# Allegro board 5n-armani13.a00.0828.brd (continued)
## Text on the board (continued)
IN2: list("[Spacing] IN2" "151.Shape to Route Keepin" "0 MIL [DEFAULT]" "0 MIL" "0.00 MIL" "DRC ERROR CLASS/IN2" "[Shape] Route Keepin/All ((-191.01 273.9) (8699.38 4792.96))" "[In2 Shape] GND ((-178.93 2335.01) (372.0 2675.16))" list(-117.680000 2460.370000) nil)@@@list("iris_chen" "2017/08/22 17:18:25" nil "P16C000357-PC" "5n-armani13.a00")@@@list("anson_lee" "2017/08/24 14:22:40" nil "P172000029-PC" "5n-armani13.a00.0824") | list("[Spacing] IN2" "17.Shape to Route Keepin" "0 MIL [DEFAULT]" "0 MIL" "0.00 MIL" "DRC ERROR CLASS/IN2" "[Shape] Route Keepin/All ((-191.01 273.9) (8699.38 4792.96))" "[In2 Shape] GND ((-190.82 3060.98) (345.0 3567.95))" list(-104.250000 3275.020000) nil)@@@list("iris_chen" "2017/08/24 17:07:00" nil "P16C000357-PC" "5n-armani13.a00")@@@list("anson_lee" "2017/08/24 14:34:00" nil "P172000029-PC" "5n-armani13.a00.0824") | list("[Spacing] IN2" "156.Shape to Route Keepin" "0 MIL [DEFAULT]" "0 MIL" "0.00 MIL" "DRC ERROR CLASS/IN2" "[Shape] Route Keepin/All ((-191.01 273.9) (8699.38 4792.96))" "[In2 Shape] AGND ((-82.35 1638.39) (320.86 2327.98))" list(-82.350000 1926.660000) nil)@@@list("iris_chen" "2017/08/22 17:18:24" nil "P16C000357-PC" "5n-armani13.a00")@@@list("anson_lee" "2017/08/24 14:22:55" nil "P172000029-PC" "5n-armani13.a00.0824") | list("[Spacing] IN2" "152.Shape to Route Keepin" "0 MIL [DEFAULT]" "0 MIL" "0.00 MIL" "DRC ERROR CLASS/IN2" "[Shape] Route Keepin/All ((-191.01 273.9) (8699.38 4792.96))" "[In2 Shape] AGND ((-76.51 2279.8) (160.91 2411.98))" list(49.770000 2279.810000) nil)@@@list("iris_chen" "2017/08/22 17:18:25" nil "P16C000357-PC" "5n-armani13.a00")@@@list("anson_lee" "2017/08/24 14:22:41" nil "P172000029-PC" "5n-armani13.a00.0824") | list("[Spacing] IN2" "155.Shape to Route Keepin" "0 MIL [DEFAULT]" "0 MIL" "0.00 MIL" "DRC ERROR CLASS/IN2" "[Shape] Route Keepin/All ((-191.01 273.9) (8699.38 4792.96))" "[In2 Shape] GND ((-190.82 3060.98) (345.0 3567.95))" list(156.280000 3192.770000) nil)@@@list("iris_chen" "2017/08/22 17:18:26" nil "P16C000357-PC" "5n-armani13.a00")@@@list("anson_lee" "2017/08/24 14:22:43" nil "P172000029-PC" "5n-armani13.a00.0824") | list("[Spacing] IN2" "153.Shape to Route Keepin" "0 MIL [DEFAULT]" "0 MIL" "0.00 MIL" "DRC ERROR CLASS/IN2" "[Shape] Route Keepin/All ((-191.01 273.9) (8699.38 4792.96))" "[In2 Shape] GND ((-82.35 352.64) (7949.09 1709.99))" list(3884.420000 504.590000) nil)@@@list("iris_chen" "2017/08/22 17:18:24" nil "P16C000357-PC" "5n-armani13.a00")@@@list("anson_lee" "2017/08/24 14:22:41" nil "P172000029-PC" "5n-armani13.a00.0824") | list("[Spacing] IN2" "154.Shape to Route Keepin" "0 MIL [DEFAULT]" "0 MIL" "0.00 MIL" "DRC ERROR CLASS/IN2" "[Shape] Route Keepin/All ((-191.01 273.9) (8699.38 4792.96))" "[In2 Shape] GND ((8039.3 273.9) (8493.57 649.68))" list(8126.570000 590.190000) nil)@@@list("iris_chen" "2017/08/22 17:18:26" nil "P16C000357-PC" "5n-armani13.a00")@@@list("anson_lee" "2017/08/24 14:22:42" nil "P172000029-PC" "5n-armani13.a00.0824")
IN3: list("[Spacing] IN3" "160.Shape to Route Keepin" "0 MIL [DEFAULT]" "0 MIL" "0.00 MIL" "DRC ERROR CLASS/IN3" "[Shape] Route Keepin/All ((-191.01 273.9) (8699.38 4792.96))" "[In3 Shape] GND ((-178.93 2335.01) (329.0 2675.16))" list(-105.120000 2487.760000) nil)@@@list("iris_chen" "2017/08/22 17:18:27" nil "P16C000357-PC" "5n-armani13.a00")@@@list("anson_lee" "2017/08/24 14:22:58" nil "P172000029-PC" "5n-armani13.a00.0824") | list("[Spacing] IN3" "158.Shape to Route Keepin" "0 MIL [DEFAULT]" "0 MIL" "0.00 MIL" "DRC ERROR CLASS/IN3" "[Shape] Route Keepin/All ((-191.01 273.9) (8699.38 4792.96))" "[In3 Shape] AGND ((-82.35 1502.72) (318.58 2427.98))" list(-6.100000 1936.570000) nil)@@@list("iris_chen" "2017/08/22 17:18:28" nil "P16C000357-PC" "5n-armani13.a00")@@@list("anson_lee" "2017/08/24 14:22:57" nil "P172000029-PC" "5n-armani13.a00.0824") | list("[Spacing] IN3" "161.Shape to Route Keepin" "0 MIL [DEFAULT]" "0 MIL" "0.00 MIL" "DRC ERROR CLASS/IN3" "[Shape] Route Keepin/All ((-191.01 273.9) (8699.38 4792.96))" "[In3 Shape] GND ((-190.82 3060.98) (302.27 3567.95))" list(156.280000 3192.770000) nil)@@@list("iris_chen" "2017/08/22 17:18:27" nil "P16C000357-PC" "5n-armani13.a00")@@@list("anson_lee" "2017/08/24 14:22:59" nil "P172000029-PC" "5n-armani13.a00.0824") | list("[Spacing] IN3" "157.Shape to Route Keepin" "0 MIL [DEFAULT]" "0 MIL" "0.00 MIL" "DRC ERROR CLASS/IN3" "[Shape] Route Keepin/All ((-191.01 273.9) (8699.38 4792.96))" "[In3 Shape] GND ((-82.35 352.64) (7949.09 1709.99))" list(3884.420000 504.590000) nil)@@@list("iris_chen" "2017/08/22 17:18:27" nil "P16C000357-PC" "5n-armani13.a00")@@@list("anson_lee" "2017/08/24 14:22:56" nil "P172000029-PC" "5n-armani13.a00.0824") | list("[Spacing] IN3" "159.Shape to Route Keepin" "0 MIL [DEFAULT]" "0 MIL" "0.00 MIL" "DRC ERROR CLASS/IN3" "[Shape] Route Keepin/All ((-191.01 273.9) (8699.38 4792.96))" "[In3 Shape] GND ((8039.3 273.9) (8493.57 649.68))" list(8126.570000 590.190000) nil)@@@list("iris_chen" "2017/08/22 17:18:28" nil "P16C000357-PC" "5n-armani13.a00")@@@list("anson_lee" "2017/08/24 14:22:58" nil "P172000029-PC" "5n-armani13.a00.0824")
GND2: list("[Spacing] GND2" "163.Shape to Route Keepin" "0 MIL [DEFAULT]" "0 MIL" "0.00 MIL" "DRC ERROR CLASS/GND2" "[Shape] Route Keepin/All ((-191.01 273.9) (8699.38 4792.96))" "[Gnd2 Shape] AGND ((-137.46 1141.0) (434.0 2428.0))" list(-129.620000 2286.830000) nil)@@@list("iris_chen" "2017/08/22 17:18:29" nil "P16C000357-PC" "5n-armani13.a00")@@@list("anson_lee" "2017/08/24 14:23:01" nil "P172000029-PC" "5n-armani13.a00.0824") | list("[Spacing-SameNet] GND2" "197.Thru Pin to Shape Same Net" "5 MIL [DEFAULT]" "0 MIL" "5.00 MIL" "DRC ERROR CLASS/GND2" "[ThruPin] GND (<uTiL>cId30<uTiL>.51) (380.5 1405.0)" "[Gnd2 Shape] GND ((-191.01 273.9) (8699.38 4792.96))" list(381.000000 1416.990000) nil)@@@list("iris_chen" "2017/08/22 17:18:47" nil "P16C000357-PC" "5n-armani13.a00")@@@list("anson_lee" "2017/08/24 14:24:03" nil "P172000029-PC" "5n-armani13.a00.0824") | list("[Spacing-SameNet] GND2" "196.Thru Pin to Shape Same Net" "5 MIL [DEFAULT]" "0 MIL" "5.00 MIL" "DRC ERROR CLASS/GND2" "[ThruPin] GND (<uTiL>cId30<uTiL>.52) (380.5 1325.5)" "[Gnd2 Shape] GND ((-191.01 273.9) (8699.38 4792.96))" list(381.000000 1337.490000) nil)@@@list("iris_chen" "2017/08/22 17:18:46" nil "P16C000357-PC" "5n-armani13.a00")@@@list("anson_lee" "2017/08/24 14:24:03" nil "P172000029-PC" "5n-armani13.a00.0824") | list("[Spacing-SameNet] GND2" "198.Thru Pin to Shape Same Net" "5 MIL [DEFAULT]" "0 MIL" "5.00 MIL" "DRC ERROR CLASS/GND2" "[ThruPin] GND (<uTiL>cId30<uTiL>.50) (380.5 1484.5)" "[Gnd2 Shape] GND ((-191.01 273.9) (8699.38 4792.96))" list(392.490000 1484.000000) nil)@@@list("iris_chen" "2017/08/22 17:18:47" nil "P16C000357-PC" "5n-armani13.a00")@@@list("anson_lee" "2017/08/24 14:24:04" nil "P172000029-PC" "5n-armani13.a00.0824") | list("[Spacing] GND2" "162.Shape to Route Keepin" "0 MIL [DEFAULT]" "0 MIL" "0.00 MIL" "DRC ERROR CLASS/GND2" "[Shape] Route Keepin/All ((-191.01 273.9) (8699.38 4792.96))" "[Gnd2 Shape] GND ((-191.01 273.9) (8699.38 4792.96))" list(3463.780000 4760.350000) nil)@@@list("iris_chen" "2017/08/22 17:18:29" nil "P16C000357-PC" "5n-armani13.a00")@@@list("anson_lee" "2017/08/24 14:23:00" nil "P172000029-PC" "5n-armani13.a00.0824") | list("[Spacing-SameNet] GND2" "200.Shape to Thru Via Same Net" "5 MIL [DEFAULT]" "0 MIL" "5.00 MIL" "DRC ERROR CLASS/GND2" "[ThruVia] GND (VIA20D10A30) (5162.0 2386.0)" "[Gnd2 Shape] GND ((-191.01 273.9) (8699.38 4792.96))" list(5160.000000 2395.800000) nil)@@@list("iris_chen" "2017/08/22 17:18:48" nil "P16C000357-PC" "5n-armani13.a00")@@@list("anson_lee" "2017/08/24 14:24:05" nil "P172000029-PC" "5n-armani13.a00.0824") | list("[Spacing-SameNet] GND2" "199.Shape to Thru Via Same Net" "5 MIL [DEFAULT]" "0 MIL" "5.00 MIL" "DRC ERROR CLASS/GND2" "[ThruVia] GND (VIA20D10A30) (5162.0 2287.54)" "[Gnd2 Shape] GND ((-191.01 273.9) (8699.38 4792.96))" list(5160.000000 2297.340000) nil)@@@list("iris_chen" "2017/08/22 17:18:48" nil "P16C000357-PC" "5n-armani13.a00")@@@list("anson_lee" "2017/08/24 14:24:05" nil "P172000029-PC" "5n-armani13.a00.0824")
NOTE: 60
User.17: agnd | gnd
User.18: +usb_typec | GND_LED | gnd | +1P8VSB | +VCCIO | vccprim | +VCCSA | +AC_BAT_SYS | +VCORE | +vddc_vga | +1VSB | +FBVDDQ | +3p3vsb | +5VSB | +5V | +3P3V | AGND
User.19: GND_LED | GND_IO | LAN_GND | agnd | gnd | Gnd_Sb
